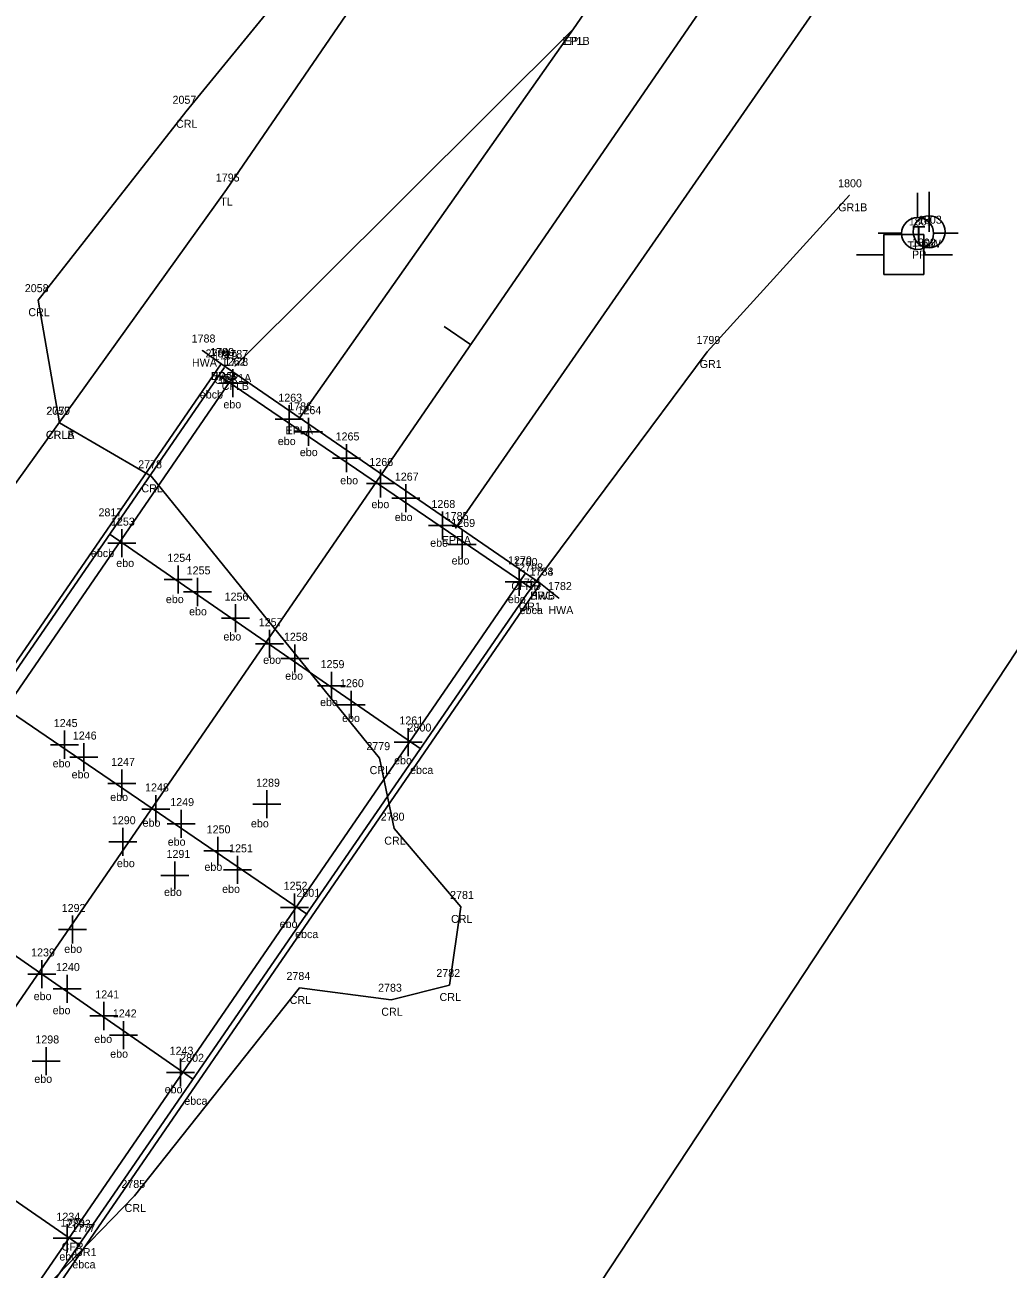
# Model space of a CAD drawing. Extents: x 2266664 to 2272542, y 716533 to 724777.
# Drawn here: x 2269168.6 to 2269291.5, y 720089.8 to 720245.2 of the extents above; entities that cross this region are included whole.
import ezdxf

# ---------------------------------------------------------------- set-up
doc = ezdxf.new("R2010")
doc.units = 0
for name, color, linetype in [('RD_EX_Bridge', 7, 'Continuous'), ('RD_EX_Bridge_txCode', 7, 'Continuous'), ('RD_EX_Conc', 7, 'Continuous'), ('RD_EX_Conc_txCode', 7, 'Continuous'), ('RD_EX_GuardRail', 7, 'Continuous'), ('RD_EX_GuardRail_txCode', 7, 'Continuous'), ('RD_EX_H2O', 7, 'Continuous'), ('RD_EX_H2O_txCode', 7, 'Continuous'), ('RD_EX_Misc', 7, 'Continuous'), ('RD_EX_Misc_txCode', 7, 'Continuous'), ('RD_EX_Road', 7, 'Continuous'), ('RD_EX_Road_txCode', 7, 'Continuous'), ('RD_EX_UT', 7, 'Continuous'), ('RD_EX_UT_txCode', 7, 'Continuous'), ('RD_EX_VEG', 7, 'Continuous'), ('RD_EX_VEG_txCode', 7, 'Continuous'), ('RD_HC_Cl', 7, 'Continuous'), ('RD_HC_Data_Tic', 7, 'Continuous'), ('RD_SMD_Locator', 7, 'Continuous')]:
    doc.layers.add(name, color=color, linetype=linetype)

msp = doc.modelspace()

# ---------------------------------------------------------------- linework, layer by layer
at = {"layer": 'RD_EX_Bridge'}
for p, q in [((2269190.84, 720204.54), (2269193.18, 720202.86)), ((2269235.38, 720173.62), (2269233.07, 720175.43))]:
    msp.add_line(p, q, dxfattribs=at)
msp.add_lwpolyline([(2269005.71, 719844.75), (2269233.07, 720175.43), (2269193.18, 720202.86), (2268965.85, 719872.44), (2269005.71, 719844.75)], dxfattribs=at)
at = {"layer": 'RD_EX_Conc'}
for points in [[(2268967.59, 719871.21), (2269010.36, 719933.37), (2269052.74, 719994.95), (2269096, 720057.76), (2269138.05, 720118.85), (2269194.93, 720201.62)], [(2269004.04, 719846.24), (2269046.75, 719908.42), (2269089.1, 719970.17), (2269131.56, 720031.81), (2269174.47, 720094.11), (2269231.14, 720176.62)]]:
    msp.add_lwpolyline(points, dxfattribs=at)
at = {"layer": 'RD_EX_GuardRail'}
for points in [[(2268966.72, 719781.34), (2268981.11, 719807.65), (2269004.56, 719845.55), (2269006.56, 719847.08), (2269048.04, 719907.43), (2269090.37, 719969.18), (2269132.94, 720030.91), (2269175.81, 720093.43), (2269231.32, 720174.06), (2269253.93, 720204.36), (2269271.7, 720223.93)], [(2268919.97, 719814.14), (2268926.75, 719820.52), (2268951.58, 719851.69), (2268966.29, 719871.68), (2268967.47, 719873.87), (2269009.19, 719934.42), (2269051.44, 719995.68), (2269094.56, 720058.42), (2269136.79, 720119.9), (2269193.57, 720202.38)]]:
    msp.add_lwpolyline(points, dxfattribs=at)
at = {"layer": 'RD_EX_H2O'}
for points in [[(2269767.93, 721284.37), (2269782.71, 721225.97), (2269785.02, 721168.24), (2269775.13, 721109.56), (2269771.2, 721081.6), (2269699.05, 720969.87), (2269639.41, 720882.16), (2269579.76, 720796.73), (2269532.34, 720714.82), (2269458.38, 720614.77), (2269435.48, 720587.45), (2269421.14, 720588.43), (2269406.07, 720569.38), (2269378.1, 720532.03), (2269376.77, 720522.5), (2269374.57, 720506.37), (2269353.14, 720462.11), (2269299.72, 720380.31), (2269223.9, 720277.28), (2269188.77, 720234.36), (2269170.31, 720210.83), (2269172.99, 720195.51)], [(2269172.99, 720195.51), (2269184.44, 720188.83), (2269212.95, 720153.63), (2269214.79, 720144.82), (2269223.14, 720135.04), (2269221.7, 720125.29), (2269214.42, 720123.45), (2269202.97, 720124.92), (2269182.34, 720098.94), (2269162.9, 720078.96), (2269130.27, 720024.93)]]:
    msp.add_lwpolyline(points, dxfattribs=at)
at = {"layer": 'RD_EX_Misc'}
for p, q in [((2269194.63, 720202.22), (2269194.63, 720198.72)), ((2269232.05, 720174.76), (2269192.86, 720201.48)), ((2269196.38, 720200.47), (2269192.88, 720200.47)), ((2269201.69, 720197.7), (2269201.69, 720194.2)), ((2269203.44, 720195.95), (2269199.94, 720195.95)), ((2269204.09, 720196.14), (2269204.09, 720192.64)), ((2269205.84, 720194.39), (2269202.34, 720194.39)), ((2269208.85, 720192.86), (2269208.85, 720189.36)), ((2269210.6, 720191.11), (2269207.1, 720191.11)), ((2269213.1, 720189.67), (2269213.1, 720186.17)), ((2269214.85, 720187.92), (2269211.35, 720187.92)), ((2269216.25, 720187.84), (2269216.25, 720184.34)), ((2269218, 720186.09), (2269214.5, 720186.09)), ((2269220.83, 720184.42), (2269220.83, 720180.92)), ((2269218.17, 720154.75), (2269179.2, 720181.63)), ((2269180.76, 720182.22), (2269180.76, 720178.72)), ((2269222.58, 720182.67), (2269219.08, 720182.67)), ((2269223.31, 720182.05), (2269223.31, 720178.55)), ((2269182.51, 720180.47), (2269179.01, 720180.47)), ((2269225.06, 720180.3), (2269221.56, 720180.3)), ((2269187.81, 720177.7), (2269187.81, 720174.2)), ((2269230.41, 720177.39), (2269230.41, 720173.89)), ((2269189.56, 720175.95), (2269186.06, 720175.95)), ((2269190.22, 720176.13), (2269190.22, 720172.63)), ((2269232.16, 720175.64), (2269228.66, 720175.64)), ((2269191.97, 720174.38), (2269188.47, 720174.38)), ((2269194.98, 720172.85), (2269194.98, 720169.35)), ((2269196.73, 720171.1), (2269193.23, 720171.1)), ((2269199.22, 720169.66), (2269199.22, 720166.16)), ((2269200.97, 720167.91), (2269197.47, 720167.91)), ((2269202.37, 720167.83), (2269202.37, 720164.33)), ((2269204.12, 720166.08), (2269200.62, 720166.08)), ((2269206.96, 720164.42), (2269206.96, 720160.92)), ((2269208.71, 720162.67), (2269205.21, 720162.67)), ((2269209.44, 720162.04), (2269209.44, 720158.54)), ((2269203.97, 720134.11), (2269164.76, 720160.82)), ((2269211.19, 720160.29), (2269207.69, 720160.29)), ((2269173.61, 720157.06), (2269173.61, 720153.56)), ((2269216.54, 720157.38), (2269216.54, 720153.88)), ((2269175.36, 720155.31), (2269171.86, 720155.31)), ((2269176.01, 720155.5), (2269176.01, 720152)), ((2269218.29, 720155.63), (2269214.79, 720155.63)), ((2269177.76, 720153.75), (2269174.26, 720153.75)), ((2269180.77, 720152.21), (2269180.77, 720148.71)), ((2269182.52, 720150.46), (2269179.02, 720150.46)), ((2269185.02, 720149.02), (2269185.02, 720145.52)), ((2269198.9, 720149.61), (2269198.9, 720146.11)), ((2269200.65, 720147.86), (2269197.15, 720147.86)), ((2269186.77, 720147.27), (2269183.27, 720147.27)), ((2269188.17, 720147.19), (2269188.17, 720143.69)), ((2269180.9, 720144.92), (2269180.9, 720141.42)), ((2269189.92, 720145.44), (2269186.42, 720145.44)), ((2269182.65, 720143.17), (2269179.15, 720143.17)), ((2269192.75, 720143.78), (2269192.75, 720140.28)), ((2269194.5, 720142.03), (2269191, 720142.03)), ((2269195.23, 720141.41), (2269195.23, 720137.91)), ((2269189.73, 720113.5), (2269150.7, 720140.54)), ((2269187.41, 720140.71), (2269187.41, 720137.21)), ((2269196.98, 720139.66), (2269193.48, 720139.66)), ((2269189.16, 720138.96), (2269185.66, 720138.96)), ((2269202.33, 720136.74), (2269202.33, 720133.24)), ((2269204.08, 720134.99), (2269200.58, 720134.99)), ((2269174.6, 720133.96), (2269174.6, 720130.46)), ((2269176.35, 720132.21), (2269172.85, 720132.21)), ((2269170.78, 720128.41), (2269170.78, 720124.91)), ((2269172.53, 720126.66), (2269169.03, 720126.66)), ((2269173.92, 720126.58), (2269173.92, 720123.08)), ((2269175.67, 720124.83), (2269172.17, 720124.83)), ((2269178.51, 720123.17), (2269178.51, 720119.67)), ((2269180.26, 720121.42), (2269176.76, 720121.42)), ((2269175.58, 720092.77), (2269136.46, 720119.68)), ((2269180.99, 720120.79), (2269180.99, 720117.29)), ((2269182.74, 720119.04), (2269179.24, 720119.04)), ((2269171.31, 720117.54), (2269171.31, 720114.04)), ((2269173.06, 720115.79), (2269169.56, 720115.79)), ((2269188.09, 720116.13), (2269188.09, 720112.63)), ((2269189.84, 720114.38), (2269186.34, 720114.38)), ((2269173.94, 720095.4), (2269173.94, 720091.9)), ((2269175.69, 720093.65), (2269172.19, 720093.65))]:
    msp.add_line(p, q, dxfattribs=at)
at = {"layer": 'RD_EX_Road'}
msp.add_line((2269194.93, 720202.61), (2269237.22, 720244.72), dxfattribs=at)
for points in [[(2269202.93, 720196.07), (2269237.22, 720244.72), (2269259.4, 720276.99), (2269259.41, 720277.21), (2269317.32, 720361.94), (2269369.05, 720437.36), (2269428.45, 720522.87), (2269487.41, 720608.15), (2269502.81, 720630.76), (2269544.96, 720692.14), (2269605.63, 720780.46), (2269663.95, 720865.82), (2269721.16, 720948.73), (2269780.45, 721034.57), (2269834.47, 721112.56), (2269853.48, 721140.68), (2269880.91, 721180.54), (2269894.87, 721200.75), (2269951.76, 721285.08), (2269965.67, 721302.04), (2269963.39, 721303.74)], [(2269222.47, 720182.37), (2269278.1, 720262.57), (2269277.83, 720263.03), (2269337.43, 720348.71), (2269393.72, 720430.44), (2269448.55, 720510.19), (2269506.62, 720593.92), (2269564.83, 720678.53), (2269625.78, 720767.57), (2269683.68, 720852.02), (2269741.8, 720936.18), (2269800.12, 721020.89), (2269854.32, 721099.54), (2269879.26, 721135.52), (2269912.84, 721184.64), (2269930.38, 721209.38), (2269961.18, 721254.67), (2269975.2, 721274.82), (2269984.48, 721289.11), (2269986.54, 721288.04)]]:
    msp.add_lwpolyline(points, dxfattribs=at)
at = {"layer": 'RD_EX_UT'}
for p, q in [((2269280.22, 720224.23), (2269280.22, 720221.16)), ((2269281.65, 720219.38), (2269281.65, 720224.38)), ((2269275.29, 720219.18), (2269278.22, 720219.18)), ((2269281.01, 720219.04), (2269276.01, 720219.04)), ((2269276.01, 720219.04), (2269276.01, 720214.04)), ((2269281.01, 720214.04), (2269281.01, 720219.04)), ((2269282.22, 720219.18), (2269285.29, 720219.18)), ((2269272.57, 720216.48), (2269276.04, 720216.48)), ((2269280.93, 720216.48), (2269284.57, 720216.48)), ((2269276.01, 720214.04), (2269281.01, 720214.04))]:
    msp.add_line(p, q, dxfattribs=at)
for centre in [(2269280.22, 720219.16), (2269281.65, 720219.38)]:
    msp.add_circle(centre, 2, dxfattribs=at)
at = {"layer": 'RD_EX_VEG'}
for points in [[(2268819.78, 719716.8), (2268871.54, 719776.21), (2269193.85, 720224.65), (2269408.57, 720538.5), (2269589.67, 720791.77), (2270047.56, 721479.8), (2270363.13, 721951.09), (2270746.65, 722498.38), (2270919.94, 722752.82), (2271017.26, 722923.37)], [(2268988.31, 719705.64), (2269316.7, 720203.55), (2269323.19, 720195.95)]]:
    msp.add_lwpolyline(points, dxfattribs=at)
at = {"layer": 'RD_HC_Cl'}
msp.add_line((2267342.91, 717471.2), (2272360.46, 724762.59), dxfattribs=at)
at = {"layer": 'RD_HC_Data_Tic'}
msp.add_line((2269224.36, 720205.28), (2269221.06, 720207.54), dxfattribs=at)
at = {"layer": 'RD_SMD_Locator'}
for centre in [(2269237.22, 720244.72), (2269237.22, 720244.72), (2269188.77, 720234.36), (2269193.85, 720224.65), (2269271.7, 720223.93), (2269170.31, 720210.83), (2269190.84, 720204.54), (2269253.93, 720204.36), (2269193.18, 720202.86), (2269193.18, 720202.86), (2269193.57, 720202.38), (2269194.93, 720202.61), (2269194.93, 720201.62), (2269172.99, 720195.51), (2269172.99, 720195.51), (2269202.93, 720196.07), (2269184.44, 720188.83), (2269222.47, 720182.37), (2269231.14, 720176.62), (2269233.07, 720175.43), (2269233.07, 720175.43), (2269231.32, 720174.06), (2269235.38, 720173.62), (2269212.95, 720153.63), (2269214.79, 720144.82), (2269223.14, 720135.04), (2269202.97, 720124.92), (2269221.7, 720125.29), (2269214.42, 720123.45), (2269182.34, 720098.94), (2269174.47, 720094.11), (2269175.81, 720093.43)]:
    msp.add_circle(centre, 0.001, dxfattribs=at)

# ---------------------------------------------------------------- texts
at = {"layer": 'RD_EX_Bridge_txCode'}
for s, p in [('1788', (2269189.49, 720205.54)), ('1790', (2269191.8, 720203.86)), ('1789', (2269191.84, 720203.86)), ('HWA', (2269189.53, 720202.54)), ('HWB', (2269191.89, 720200.86)), ('BRC', (2269191.93, 720200.86)), ('1783', (2269231.73, 720176.43)), ('1784', (2269231.73, 720176.43)), ('1782', (2269234.03, 720174.62)), ('HWB', (2269231.78, 720173.43)), ('BRC', (2269231.82, 720173.43)), ('HWA', (2269234.07, 720171.62))]:
    msp.add_text(s, height=1, dxfattribs=at).set_placement(p)
at = {"layer": 'RD_EX_Conc_txCode'}
for s, p in [('1778', (2269193.58, 720202.62)), ('CFLB', (2269193.25, 720199.62)), ('1780', (2269229.75, 720177.62)), ('CFRB', (2269229.44, 720174.62)), ('1776', (2269173.1, 720095.11)), ('CFR', (2269173.24, 720092.11))]:
    msp.add_text(s, height=1, dxfattribs=at).set_placement(p)
at = {"layer": 'RD_EX_GuardRail_txCode'}
for s, p in [('1800', (2269270.28, 720224.93)), ('GR1B', (2269270.29, 720221.93)), ('1799', (2269252.58, 720205.36)), ('1779', (2269192.22, 720203.38)), ('GR1', (2269252.98, 720202.36)), ('GRB', (2269192.32, 720200.38)), ('1781', (2269230.26, 720175.06)), ('GR1', (2269230.38, 720172.06)), ('1777', (2269174.46, 720094.43)), ('GR1', (2269174.86, 720091.43))]:
    msp.add_text(s, height=1, dxfattribs=at).set_placement(p)
at = {"layer": 'RD_EX_H2O_txCode'}
for s, p in [('2057', (2269187.1, 720235.36)), ('CRL', (2269187.54, 720232.36)), ('2058', (2269168.64, 720211.83)), ('CRL', (2269169.08, 720208.83)), ('2059', (2269171.32, 720196.51)), ('2777', (2269171.36, 720196.51)), ('CRLA', (2269171.27, 720193.51)), ('CRLB', (2269171.28, 720193.51)), ('2778', (2269182.81, 720189.83)), ('CRL', (2269183.21, 720186.83)), ('2779', (2269211.32, 720154.63)), ('CRL', (2269211.73, 720151.63)), ('2780', (2269213.12, 720145.82)), ('CRL', (2269213.56, 720142.82)), ('2781', (2269221.79, 720136.04)), ('CRL', (2269221.91, 720133.04)), ('2782', (2269220.07, 720126.29)), ('2784', (2269201.34, 720125.92)), ('2783', (2269212.79, 720124.45)), ('CRL', (2269220.47, 720123.29)), ('CRL', (2269201.74, 720122.92)), ('CRL', (2269213.19, 720121.45)), ('2785', (2269180.71, 720099.94)), ('CRL', (2269181.11, 720096.94))]:
    msp.add_text(s, height=1, dxfattribs=at).set_placement(p)
at = {"layer": 'RD_EX_Misc_txCode'}
for s, p in [('2799', (2269191.23, 720203.68)), ('1262', (2269193.26, 720202.67)), ('ebcb', (2269190.51, 720198.55)), ('1263', (2269200.32, 720198.15)), ('ebo', (2269193.46, 720197.32)), ('1264', (2269202.72, 720196.59)), ('1265', (2269207.48, 720193.31)), ('ebo', (2269200.26, 720192.73)), ('ebo', (2269203.01, 720191.35)), ('1266', (2269211.7, 720190.12)), ('1267', (2269214.88, 720188.29)), ('ebo', (2269208.06, 720187.83)), ('2817', (2269177.85, 720183.83)), ('ebo', (2269211.96, 720184.85)), ('1268', (2269219.46, 720184.87)), ('1253', (2269179.41, 720182.67)), ('ebo', (2269214.87, 720183.24)), ('1269', (2269221.94, 720182.5)), ('ebo', (2269219.3, 720180.03)), ('ebcb', (2269176.9, 720178.74)), ('ebo', (2269180.07, 720177.5)), ('1254', (2269186.46, 720178.15)), ('ebo', (2269221.98, 720177.81)), ('1270', (2269229.03, 720177.84)), ('1255', (2269188.87, 720176.58)), ('2798', (2269230.42, 720176.96)), ('ebo', (2269186.27, 720172.99)), ('1256', (2269193.61, 720173.3)), ('ebo', (2269229.01, 720172.99)), ('ebo', (2269189.17, 720171.46)), ('ebca', (2269230.48, 720171.62)), ('1257', (2269197.88, 720170.11)), ('ebo', (2269193.46, 720168.32)), ('1258', (2269201.02, 720168.28)), ('ebo', (2269198.43, 720165.41)), ('ebo', (2269201.18, 720163.42)), ('1259', (2269205.61, 720164.87)), ('1260', (2269208.03, 720162.49)), ('ebo', (2269205.54, 720160.13)), ('1245', (2269172.26, 720157.51)), ('ebo', (2269208.29, 720158.14)), ('1261', (2269215.45, 720157.83)), ('1246', (2269174.64, 720155.95)), ('2800', (2269216.47, 720156.95)), ('ebo', (2269172.12, 720152.48)), ('1247', (2269179.43, 720152.66)), ('ebo', (2269214.79, 720152.86)), ('ebo', (2269174.49, 720151.1)), ('ebca', (2269216.79, 720151.65)), ('1248', (2269183.67, 720149.47)), ('1289', (2269197.55, 720150.06)), ('ebo', (2269179.31, 720148.27)), ('1249', (2269186.82, 720147.64)), ('1290', (2269179.52, 720145.37)), ('ebo', (2269183.36, 720145.06)), ('ebo', (2269196.9, 720144.98)), ('1250', (2269191.37, 720144.23)), ('ebo', (2269186.5, 720142.69)), ('1251', (2269194.17, 720141.86)), ('1291', (2269186.35, 720141.16)), ('ebo', (2269180.15, 720140.01)), ('ebo', (2269191.09, 720139.55)), ('1252', (2269200.99, 720137.19)), ('ebo', (2269186.04, 720136.41)), ('ebo', (2269193.3, 720136.79)), ('2801', (2269202.58, 720136.31)), ('1292', (2269173.25, 720134.41)), ('ebo', (2269200.49, 720132.43)), ('ebca', (2269202.42, 720131.15)), ('ebo', (2269173.57, 720129.3)), ('1239', (2269169.43, 720128.86)), ('1240', (2269172.54, 720127.03)), ('ebo', (2269169.75, 720123.4)), ('1241', (2269177.45, 720123.62)), ('ebo', (2269172.12, 720121.64)), ('1242', (2269179.64, 720121.24)), ('1298', (2269169.96, 720117.99)), ('ebo', (2269177.32, 720118.05)), ('ebo', (2269179.31, 720116.21)), ('1243', (2269186.74, 720116.58)), ('2802', (2269188.06, 720115.7)), ('ebo', (2269169.83, 720113.07)), ('ebo', (2269186.12, 720111.77)), ('ebca', (2269188.57, 720110.33)), ('1234', (2269172.59, 720095.85)), ('2803', (2269173.91, 720094.97)), ('ebo', (2269172.96, 720090.88)), ('ebca', (2269174.58, 720089.9))]:
    msp.add_text(s, height=1, dxfattribs=at).set_placement(p)
at = {"layer": 'RD_EX_Road_txCode'}
for s, p in [('EP1B', (2269235.82, 720242.72)), ('EPL', (2269236.01, 720242.72)), ('1787', (2269193.58, 720203.61)), ('EP1A', (2269193.52, 720200.61)), ('1786', (2269201.56, 720197.07)), ('EPLA', (2269201.23, 720194.07)), ('1785', (2269221.12, 720183.37)), ('EPRA', (2269220.75, 720180.37))]:
    msp.add_text(s, height=1, dxfattribs=at).set_placement(p)
at = {"layer": 'RD_EX_UT'}
msp.add_text('T', height=2, dxfattribs=at).set_placement((2269279.55, 720218.11))
at = {"layer": 'RD_EX_UT_txCode'}
for s, p in [('1801', (2269279.12, 720220.16)), ('1803', (2269280.26, 720220.38)), ('TPP', (2269278.95, 720217.16)), ('1802', (2269279.51, 720217.53)), ('GW', (2269280.81, 720217.38)), ('PP', (2269279.51, 720216.03))]:
    msp.add_text(s, height=1, dxfattribs=at).set_placement(p)
at = {"layer": 'RD_EX_VEG_txCode'}
for s, p in [('1795', (2269192.51, 720225.65)), ('TL', (2269193.08, 720222.65))]:
    msp.add_text(s, height=1, dxfattribs=at).set_placement(p)

doc.saveas('drawing.dxf')
